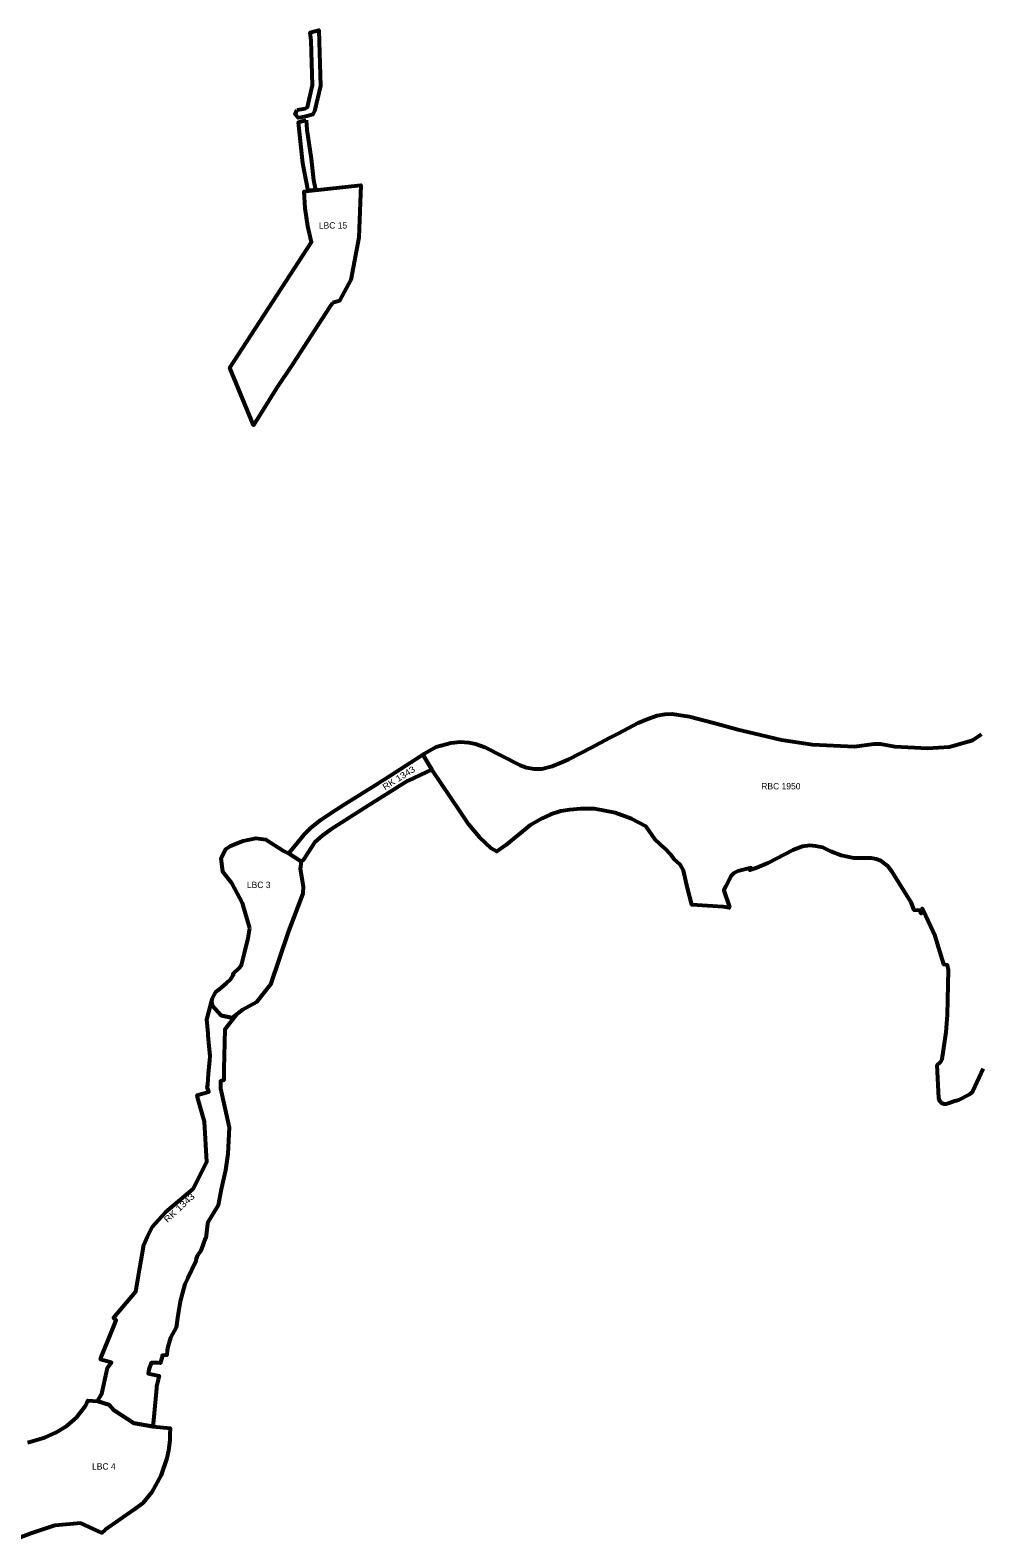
# Model space of a CAD drawing. Extents: x -650276 to -642570, y -1074314 to -1066553.
# Drawn here: x -646294 to -644496, y -1070338 to -1067493 of the extents above; entities that cross this region are included whole.
import ezdxf
from ezdxf.enums import TextEntityAlignment as Align

# ---------------------------------------------------------------- set-up
doc = ezdxf.new("R2010")
doc.units = 0
doc.header["$LTSCALE"] = 4.8
for name, color, linetype, lineweight in [('15', 7, 'Continuous', 53), ('19', 7, 'Continuous', 53), ('23', 7, 'Continuous', 53), ('27', 7, 'Continuous', 53), ('29', 7, 'Continuous', 53)]:
    doc.layers.add(name, color=color, linetype=linetype, lineweight=lineweight)
doc.layers.add('63', color=7, linetype='Continuous')

msp = doc.modelspace()

# ---------------------------------------------------------------- linework, layer by layer
at = {"layer": '15'}
for points in [[(-645275.45, -1068964.38), (-645292.77, -1068966.91), (-645311.99, -1068972.74), (-645328.55, -1068980.37), (-645350.17, -1068993.33), (-645372.67, -1069011.7), (-645371.56, -1069010.81), (-645396.53, -1069030.88), (-645413.29, -1069042.92), (-645423.51, -1069037.41), (-645446.14, -1069015.65), (-645466.03, -1068991.95), (-645482.49, -1068967.44), (-645535.87, -1068888.03), (-645540.97, -1068879.83), (-645553.3, -1068860.01), (-645527.84, -1068845.59), (-645499.8, -1068838.07), (-645482.88, -1068835.58), (-645466.2, -1068836.84), (-645453.59, -1068839.38), (-645436.18, -1068845.91), (-645369.07, -1068879.97), (-645357.42, -1068884.27), (-645342.95, -1068887.14), (-645328.6, -1068886.89), (-645309.08, -1068881.71), (-645290.63, -1068873.98), (-645277.52, -1068868.49), (-645234.68, -1068846.67), (-645200.52, -1068828.2), (-645183.29, -1068819.23), (-645146.79, -1068800.21), (-645128.2, -1068792.33), (-645110.5, -1068786.08), (-645096.42, -1068783.56), (-645082.62, -1068782.8), (-645050.5, -1068788.01), (-645004.48, -1068800.3), (-644958.68, -1068812.54), (-644928.99, -1068819.58), (-644875.93, -1068832.15), (-644817.51, -1068840.81), (-644738.26, -1068844.61), (-644700.9, -1068839.57), (-644689.35, -1068839.45), (-644661.88, -1068844.68), (-644600.36, -1068847.65), (-644558.97, -1068845.61), (-644521.21, -1068834.8), (-644515.35, -1068832.94), (-644498.216, -1068821.641)], [(-644495.46, -1069453.11), (-644514.85, -1069495), (-644517.06, -1069498.44), (-644520.98, -1069501.79), (-644542.01, -1069512), (-644548.78, -1069514.21), (-644561.24, -1069518.27), (-644566.01, -1069519.75), (-644569.16, -1069519.63), (-644572.75, -1069518.39), (-644577.16, -1069514.36), (-644579.1, -1069508.42), (-644581.87, -1069446.28), (-644575.93, -1069440.66), (-644572.97, -1069435.12), (-644565.02, -1069383.98), (-644562.55, -1069350.97), (-644560.58, -1069265.94), (-644562.47, -1069257.56), (-644569.73, -1069256.28), (-644586.03, -1069202.7), (-644603.57, -1069164.82), (-644610.16, -1069150.6), (-644612.86, -1069156.82), (-644612.3, -1069159.66), (-644613.58, -1069155.95), (-644615.11, -1069154.11), (-644625.34, -1069153.31), (-644631.12, -1069138.5), (-644666.82, -1069081.36), (-644675.02, -1069070.3), (-644688.27, -1069060.62), (-644697.5, -1069057.16), (-644706.99, -1069055.45), (-644739.62, -1069055.42), (-644763.63, -1069050.17), (-644783.05, -1069042.69), (-644797.84, -1069035.56), (-644811.66, -1069032.56), (-644822.43, -1069031.81), (-644836.38, -1069033.69), (-644854.3, -1069040.5), (-644901.69, -1069064.96), (-644922.7, -1069073.95), (-644935.81, -1069078.12), (-644932.95, -1069073.65), (-644958.25, -1069079.99), (-644965.95, -1069083.67), (-644970.84, -1069088.8), (-644981.3, -1069108.22), (-644985.15, -1069116.67), (-644974.34, -1069147.85), (-644974.505, -1069149.05), (-644986.221, -1069147.139), (-645044.97, -1069143.38), (-645053.61, -1069112.32), (-645061.2, -1069078.47), (-645067.57, -1069067.16), (-645078.47, -1069057.37), (-645084.19, -1069049.55), (-645096.97, -1069036.63), (-645114.52, -1069020.11), (-645131.73, -1068995.69), (-645159.37, -1068981.11), (-645189.84, -1068969.91), (-645229.27, -1068962.28), (-645255.21, -1068962.49), (-645275.45, -1068964.38)]]:
    msp.add_lwpolyline(points, dxfattribs=at)
at = {"layer": '19'}
for points in [[(-645806.26, -1069046.58), (-645803.29, -1069042.92), (-645790.53, -1069027.19), (-645777.16, -1069010.72), (-645770.47, -1069003.97), (-645764.17, -1068997.62), (-645745.65, -1068982.8), (-645726.46, -1068970.04), (-645699.5, -1068953.13), (-645637.82, -1068914.25), (-645630.48, -1068909.6), (-645623.92, -1068905.45), (-645557.17, -1068862.39), (-645553.3, -1068860.01), (-645540.97, -1068879.83), (-645535.87, -1068888.03), (-645581.58, -1068909.41), (-645655.69, -1068956.35), (-645726.85, -1069001.34), (-645742.5, -1069012.99), (-645757.51, -1069026.02), (-645770.04, -1069045.34), (-645777.73, -1069057.2), (-645779.49, -1069059.92), (-645783.02, -1069061.84), (-645784.69, -1069060.74)], [(-646167.42, -1070080.12), (-646159.14, -1070066.71), (-646148.34, -1070017.73), (-646141.14, -1070007.63), (-646161.71, -1070001.55), (-646160.09, -1069997.51), (-646152.59, -1069978.9), (-646136.46, -1069938.84), (-646135.28, -1069935.88), (-646131.96, -1069927.57), (-646136.23, -1069923.94), (-646136.88, -1069923.39), (-646094.82, -1069873.63), (-646091.72, -1069854.99), (-646088.02, -1069832.44), (-646085.07, -1069814.68), (-646080.14, -1069785.63), (-646072.6, -1069769.62), (-646063.59, -1069750.57), (-646051.95, -1069738.02), (-646038.48, -1069723.16), (-645986.71, -1069679.91), (-645961.36, -1069630.05), (-645960.78, -1069628.91), (-645965.36, -1069552.99), (-645977.73, -1069509.11), (-645978.852, -1069502.689), (-645957.35, -1069496.35), (-645958.57, -1069492.51), (-645960.18, -1069487.45), (-645959.32, -1069483.43), (-645959.32, -1069483.43), (-645957.52, -1069461.75), (-645955.52, -1069437.7), (-645954.74, -1069428.36), (-645956.97, -1069404), (-645958.23, -1069390.23), (-645958.59, -1069386.32), (-645961.03, -1069359.69), (-645952.303, -1069326.378), (-645949.992, -1069334.461), (-645933.792, -1069352.53), (-645913.23, -1069356.892), (-645905.079, -1069350.779), (-645926.91, -1069378.79), (-645928.53, -1069453.3), (-645928.99, -1069474.55), (-645935.05, -1069476.32), (-645935.03, -1069480.02), (-645935, -1069485.04), (-645934.97, -1069490.31), (-645918.82, -1069563.81), (-645921.18, -1069613.78), (-645925.69, -1069644.69), (-645933.68, -1069680.28), (-645939.36, -1069710.47), (-645958.9, -1069742.7), (-645959.35, -1069745.74), (-645963.06, -1069772.82), (-645964.34, -1069773.6), (-645967.15, -1069781.97), (-645968.57, -1069785.9), (-645972.16, -1069795.77), (-645979.38, -1069805.93), (-645980.87, -1069811.56), (-645982.12, -1069817.85), (-645996.72, -1069847.96), (-646002.25, -1069859.77), (-646011.51, -1069892.38), (-646015.46, -1069918.63), (-646018.88, -1069941.32), (-646029.65, -1069960.92), (-646035.42, -1069980.12), (-646035.75, -1069984.73), (-646036.36, -1069993.34), (-646045.27, -1069994.44), (-646045.22, -1069996.81), (-646048.71, -1070008.77), (-646053.4, -1070007.98), (-646066.06, -1070008.11), (-646070.67, -1070020.78), (-646071.32, -1070024.95), (-646071.84, -1070028.3), (-646050.67, -1070032.37), (-646052.63, -1070039.21), (-646055.78, -1070052.52), (-646056.09, -1070055.76), (-646060.36, -1070103.99), (-646062.8, -1070128.04), (-646098.96, -1070122.04), (-646136.41, -1070097.53), (-646145.47, -1070087.27)]]:
    msp.add_lwpolyline(points, close=True, dxfattribs=at)
at = {"layer": '23'}
for points in [[(-645723.79, -1068007.07), (-645729.57, -1068015.25), (-645798.69, -1068122.17), (-645829.66, -1068168.34), (-645872.64, -1068238.08), (-645917.44, -1068129.99), (-645763.31, -1067892.76), (-645769.95, -1067862.62), (-645775.45, -1067828.44), (-645777.308, -1067797.119), (-645768.11, -1067795.54), (-645670.064, -1067785.335), (-645673.827, -1067884.119), (-645688.88, -1067964.087), (-645710.519, -1068003.601)], [(-645879.84, -1069187.64), (-645883.39, -1069175.24), (-645893.36, -1069140.52), (-645898.3, -1069130.96), (-645913.85, -1069102.71), (-645930.96, -1069081.23), (-645933.84, -1069055.44), (-645925.49, -1069038.22), (-645915.93, -1069031.93), (-645892.13, -1069022.51), (-645868.65, -1069017.82), (-645849.73, -1069020.52), (-645815.87, -1069041.86), (-645806.26, -1069046.58), (-645784.69, -1069060.74), (-645783.02, -1069061.84), (-645784.52, -1069075.66), (-645778.75, -1069108.98), (-645779.685, -1069122.296), (-645806.806, -1069193.112), (-645840.644, -1069294.052), (-645867.026, -1069327.317), (-645893.291, -1069341.938), (-645913.23, -1069356.892), (-645933.792, -1069352.53), (-645949.992, -1069334.461), (-645952.303, -1069326.378), (-645950.49, -1069319.46), (-645947.21, -1069313.26), (-645943.67, -1069307.84), (-645936.46, -1069301.94), (-645932.07, -1069298.43), (-645923.56, -1069291.6), (-645916.39, -1069284.67), (-645910.4, -1069275.66), (-645911.64, -1069274.48), (-645898.96, -1069262.45), (-645898.67, -1069262.02), (-645895.95, -1069257.98), (-645895.25, -1069257.41), (-645888.98, -1069232.44), (-645882.56, -1069206.54)]]:
    msp.add_lwpolyline(points, close=True, dxfattribs=at)
msp.add_lwpolyline([(-646298.56, -1070158.26), (-646266.83, -1070149.27), (-646245.94, -1070139.49), (-646225.41, -1070126.72), (-646215.99, -1070118.79), (-646207.09, -1070111.31), (-646189.94, -1070089.25), (-646185.32, -1070079.18), (-646167.42, -1070080.12), (-646145.47, -1070087.27), (-646136.41, -1070097.53), (-646098.96, -1070122.04), (-646062.8, -1070128.04), (-646029.864, -1070131.413), (-646030.51, -1070143.17), (-646030.66, -1070153.86), (-646033.06, -1070173.32), (-646036.61, -1070187.84), (-646047.55, -1070221.59), (-646064.78, -1070252.22), (-646081.74, -1070273.1), (-646098.57, -1070285.71), (-646152.57, -1070323.39), (-646159.26, -1070328.75), (-646198.52, -1070310.669), (-646247.667, -1070315.004), (-646293.14, -1070330.3), (-646314.84, -1070338.41)], dxfattribs=at)
at = {"layer": '27'}
msp.add_lwpolyline([(-645773.23, -1067662.67), (-645771.86, -1067680.92), (-645763.92, -1067735.14), (-645759.32, -1067775.89), (-645755.758, -1067794.254), (-645769.602, -1067795.796), (-645779.64, -1067743.41), (-645780.39, -1067737.84), (-645787.55, -1067666.46)], close=True, dxfattribs=at)
at = {"layer": '29'}
for points in [[(-645790.381, -1067643.17), (-645775.114, -1067640.43), (-645770.809, -1067637.786), (-645761.499, -1067596.501), (-645764.084, -1067511.925), (-645765.859, -1067496.872), (-645749.67, -1067492.54), (-645748.994, -1067514.663)], [(-645748.994, -1067514.663), (-645746.448, -1067597.944), (-645757.79, -1067645.206), (-645760.67, -1067652.05), (-645772.13, -1067655.13), (-645782.72, -1067657.28)], [(-645782.72, -1067657.28), (-645788.395, -1067658.038), (-645793.94, -1067651.61), (-645790.381, -1067643.17)]]:
    msp.add_lwpolyline(points, dxfattribs=at)

# ---------------------------------------------------------------- texts
at = {"layer": '63'}
for s, p in [('LBC 15', (-645722.709, -1067867.044)), ('RBC 1950', (-644877.184, -1068925.671)), ('LBC 3', (-645862.946, -1069111.949)), ('LBC 4', (-646155.337, -1070209.573))]:
    msp.add_text(s, height=12, dxfattribs=at).set_placement(p, align=Align.CENTER)
for rotation, width, p in [(32.163, 1.1, (-645595.379, -1068909.273)), (42.958, 1.15, (-646009.018, -1069719.932))]:
    msp.add_text('RK 1343', height=12, rotation=rotation, dxfattribs=dict(at, width=width)).set_placement(p, align=Align.CENTER)

doc.saveas('drawing.dxf')
